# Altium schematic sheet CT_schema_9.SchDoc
size 274 x 160 mm
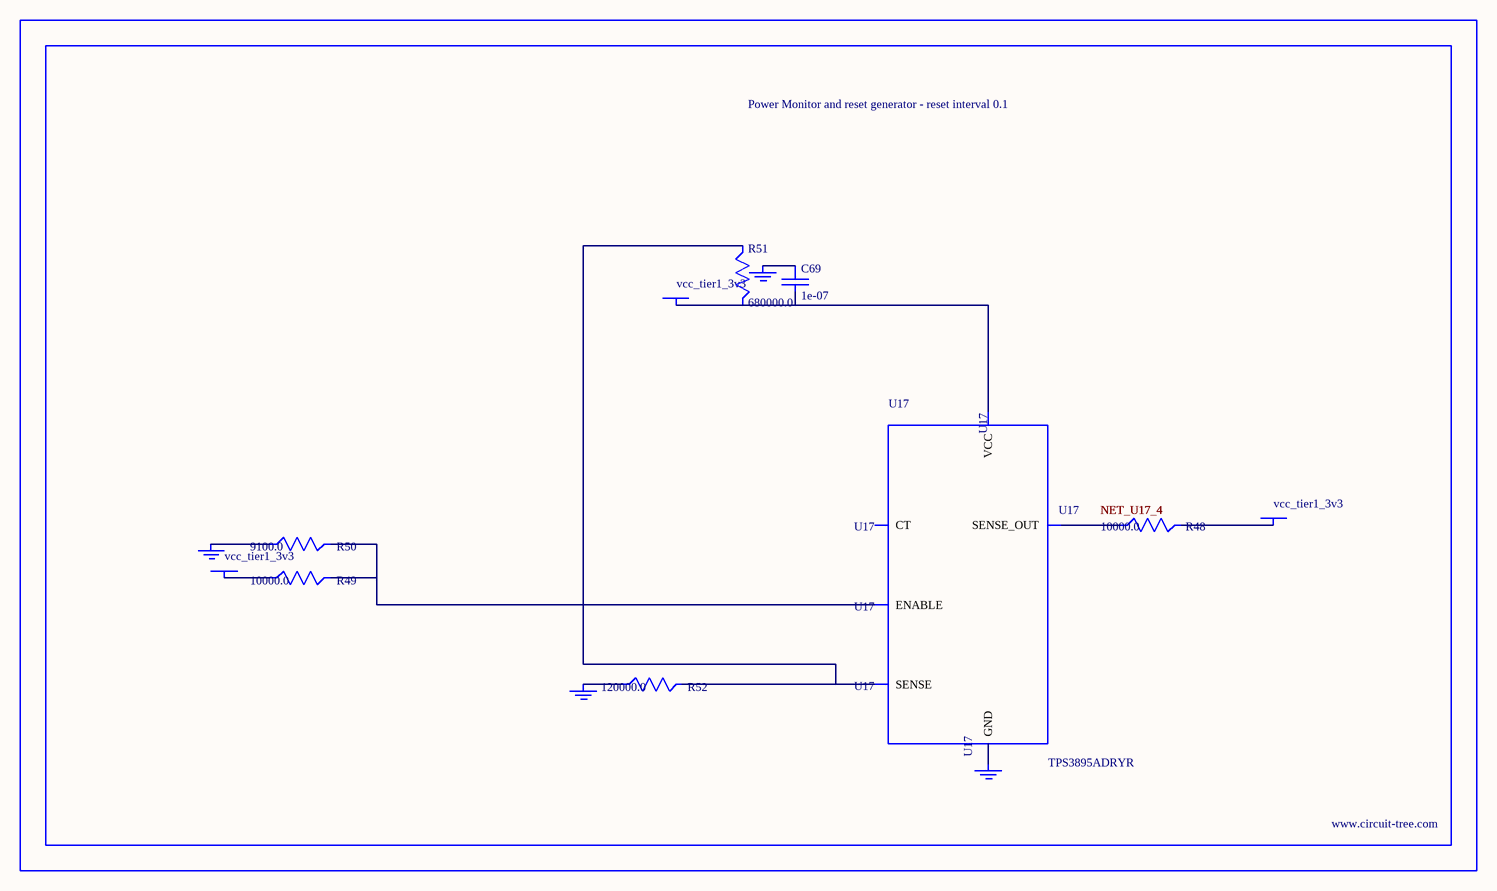
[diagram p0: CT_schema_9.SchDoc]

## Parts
BORDER8  (no value)
C69  1e-07  [C0402]
GND_INSTANCE_8_0  (no value)
GND_INSTANCE_8_1  (no value)
GND_INSTANCE_8_2  (no value)
GND_INSTANCE_8_3  (no value)
POWER_INSTANCE_8_0  vcc_tier1_3v3
POWER_INSTANCE_8_1  vcc_tier1_3v3
POWER_INSTANCE_8_2  vcc_tier1_3v3
R48  10000.0  [R0603]
R49  10000.0  [R0603]
R50  9100.0  [R0603]
R51  680000.0  [R0603]
R52  120000.0  [R0603]
U17  TPS3895ADRYR  [SON-6]

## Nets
NetC69_1: C69.1 GND_INSTANCE_8_2.0(GND)
NetC69_2: C69.2 POWER_INSTANCE_8_2.0(PWR) R51.2 U17.6(VCC)
NetGND_INSTANCE_8_0_0: GND_INSTANCE_8_0.0(GND) R50.1
NetGND_INSTANCE_8_1_0: GND_INSTANCE_8_1.0(GND) R52.1
NetGND_INSTANCE_8_3_0: GND_INSTANCE_8_3.0(GND) U17.2(GND)
NetPOWER_INSTANCE_8_0_0: POWER_INSTANCE_8_0.0(PWR) R49.1
NetPOWER_INSTANCE_8_1_0: POWER_INSTANCE_8_1.0(PWR) R48.2
NetR48_1: R48.1 U17.4(SENSE_OUT)
NetR49_2: R49.2 R50.2 U17.1(ENABLE)
NetR51_1: R51.1 R52.2 U17.3(SENSE)

Not connected (* = marked no-connect by the designer): U17 5(CT)

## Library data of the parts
BORDER8 = BORDER_PAGE8
C69 = C0402C104K3RACTU
GND_INSTANCE_8_0-GND_INSTANCE_8_3 = GND
POWER_INSTANCE_8_0-POWER_INSTANCE_8_2 = PWR
R48 R49 = RC0603JR-0710KL
R50 = RC0603JR-079K1L
R51 = RC0603JR-07680KL
R52 = RC0603JR-07120KL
